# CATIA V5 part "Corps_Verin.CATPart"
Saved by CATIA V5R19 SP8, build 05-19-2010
Part number: Corps_Verin
Bounding box of the stored display mesh (mm): x 0 to 150, y -17.5 to 17.5, z -17.322 to 17.322
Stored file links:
  G:\EU_thinkMotion\CFAO_2010\MMS_groupe1\MMS_groupe1\OK\vduret\vduret\CATIA\Corps_Verin.CATPart
  G:\EU_thinkMotion\CFAO_2010\MMS_groupe1\MMS_groupe1\OK\vduret\vduret\CATIA\Profile_bati.CATPart
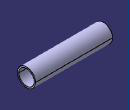
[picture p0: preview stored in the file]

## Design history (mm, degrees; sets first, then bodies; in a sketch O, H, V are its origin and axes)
Parameters
  Longueur_corps_verin = 150 mm
  Diam_corps_verin = 35 mm
  Diam_tige_verin = 20 mm
  Diam_piston_verin = 30 mm
External parameters (linked from other documents)
  External.Largeur_bati = 500 mm
Body1 (main body)
  Sketch1 on yz-plane, origin (0, 0, 0), H (0, 1, 0), V (0, 0, 1)
    circle A1 centre (0, 0) radius 17.5
    radius A1 = 17.5 {= Diam_corps_verin /2}
  Pad1: profile Sketch1, direction (1, 0, 0), length 150 {= Longueur_corps_verin}
  Sketch2 on start face of Pad1, origin (0, 0, 0), H (0, -1, 0), V (0, 0, 1)
    circle A1 centre (0, 0) radius 10
    reference projected circle E1 centre (0, 0) radius 17.5 from edge [start face of Pad1 | face of Pad1 from Sketch1.A1]
    radius A1 = 10 {= Diam_tige_verin /2}
    concentricity: A1 E1
  Pocket1: profile Sketch2, direction (1, 0, 0), through (limit type 3)
  Sketch3 on end face of Pad1, origin (150, 0, 0), H (0, 1, 0), V (0, 0, 1)
    circle A1 centre (0, 0) radius 15
    reference projected circle E1 centre (0, 0) radius 17.5 from edge [face of Pad1 from Sketch1.A1 | end face of Pad1]
    radius A1 = 15 {= Diam_piston_verin /2}
    concentricity: A1 E1
  Pocket2: profile Sketch3, direction (-1, 0, 0), length 145 {= Longueur_corps_verin -5mm}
